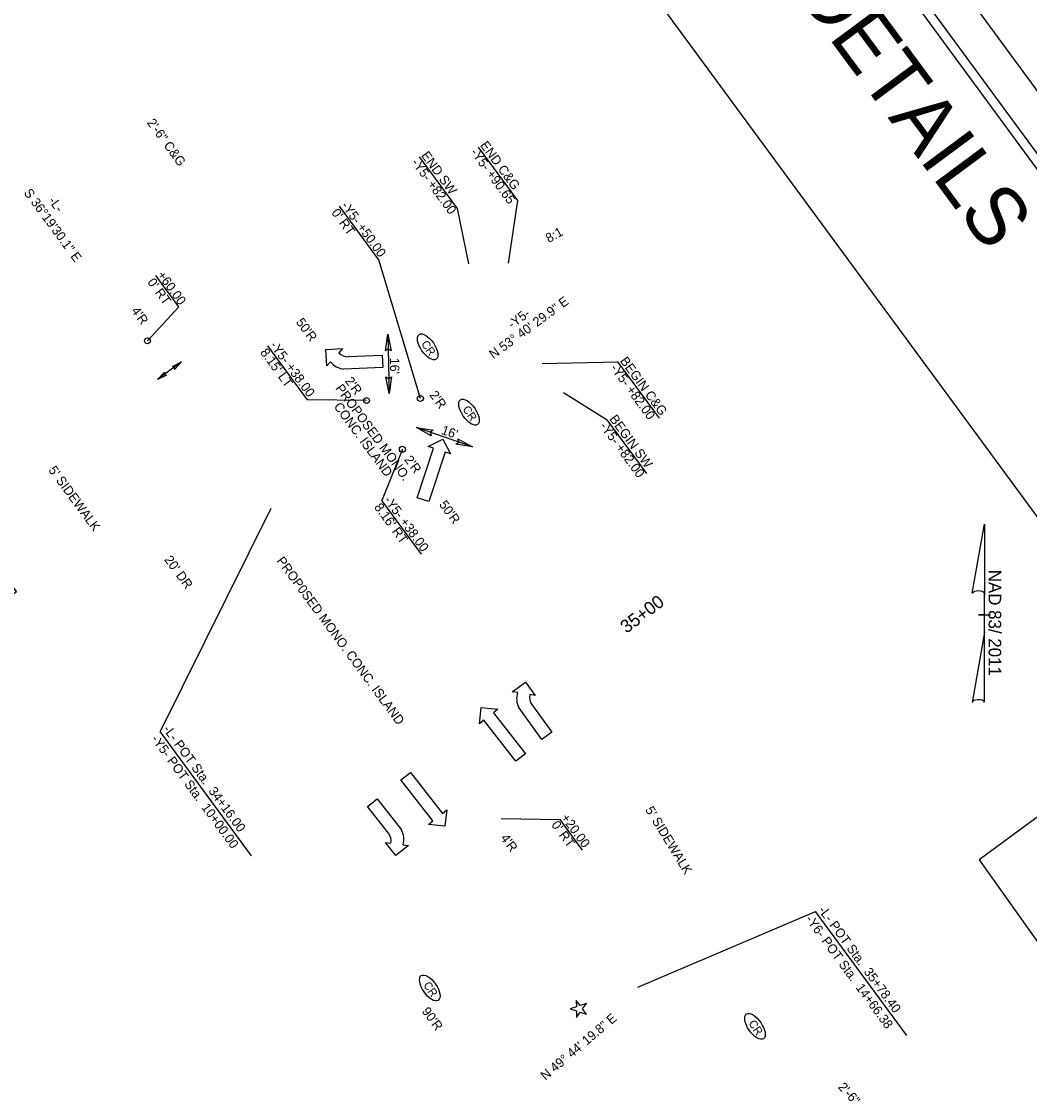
# Model space of a CAD drawing. Extents: x 1763480 to 1764420, y 711010 to 712012.
# Drawn here: x 1763983.9 to 1764255.2, y 711284 to 711573.4 of the extents above; entities that cross this region are included whole.
import ezdxf

# ---------------------------------------------------------------- set-up
doc = ezdxf.new("R2010")
doc.units = 0
for name, color, linetype in [('Default', 7, 'Continuous'), ('P-WATER', 7, 'Continuous'), ('Prop Conc 4in Sidewalk', 7, 'Continuous'), ('Prop Grid Mask', 7, 'Continuous'), ('Prop Horizontal Alignment Direction Label', 7, 'Continuous'), ('Prop Horizontal Alignment Station Label', 7, 'Continuous'), ('Prop Horizontal Alignment Tick Label', 7, 'Continuous'), ('Prop Lane Arrow CELL', 7, 'Continuous'), ('Prop North Arrow NAD83 for Plan Sheets CELL', 7, 'Continuous'), ('Prop RDY Traffic Signal CELL', 7, 'Continuous'), ('Prop Rem of Exist Asph Pvmt', 7, 'Continuous'), ('Prop Terminator CELL', 7, 'Continuous'), ('Prop WCC CELL', 7, 'Continuous'), ('Sheet Plot Border Inside CELL', 7, 'Continuous'), ('Sheet Plot Border Outside CELL', 7, 'Continuous')]:
    doc.layers.add(name, color=color, linetype=linetype)

msp = doc.modelspace()

# ---------------------------------------------------------------- linework, layer by layer
at = {"layer": 'P-WATER'}
msp.add_lwpolyline([(1764402.04, 711336.79), (1763957.77, 711941.04), (1763535.55, 711630.61), (1763979.82, 711026.35)], close=True, dxfattribs=at)
at = {"layer": 'Prop Conc 4in Sidewalk'}
for p, q in [((1764101.28, 711523.01), (1764091, 711536.96)), ((1764104.31, 711508.19), (1764101.28, 711523.01)), ((1764129.78, 711473.55), (1764141.52, 711466.2)), ((1764152.22, 711451.69), (1764141.52, 711466.2))]:
    msp.add_line(p, q, dxfattribs=at)
at = {"layer": 'Prop Grid Mask'}
for p, q in [((1764117.5, 711525.24), (1764106.92, 711539.59)), ((1764114.96, 711508.32), (1764117.5, 711525.24)), ((1764080.11, 711509.26), (1764069.53, 711523.66)), ((1764091.27, 711471.92), (1764080.11, 711509.26)), ((1764026.23, 711496.57), (1764020.05, 711504.98)), ((1764017.81, 711487.42), (1764026.23, 711496.57)), ((1764082.53, 711489.22), (1764082.85, 711473.23)), ((1764060.88, 711471.54), (1764050.18, 711486.1)), ((1764026.96, 711481.73), (1764020.51, 711476.99)), ((1764124.07, 711481.32), (1764144.43, 711481.77)), ((1764155.59, 711466.63), (1764144.43, 711481.77)), ((1764076.77, 711471.38), (1764060.88, 711471.54)), ((1764105.33, 711458.86), (1764090.21, 711464.09)), ((1764086.43, 711458.24), (1764080.93, 711444.46)), ((1764091.56, 711430.01), (1764080.93, 711444.46)), ((1764113.05, 711358.86), (1764128.88, 711358.63)), ((1764134.94, 711350.38), (1764128.88, 711358.63))]:
    msp.add_line(p, q, dxfattribs=at)
for centre in [(1764017.81, 711487.42), (1764076.77, 711471.38), (1764091.27, 711471.92), (1764086.43, 711458.24)]:
    msp.add_circle(centre, 0.802, dxfattribs=at)
at = {"layer": 'Prop Horizontal Alignment Station Label'}
msp.add_lwpolyline([(1763957.77, 711941.04), (1764052.94, 711811.6), (1764008.24, 711778.74), (1764295.85, 711387.56), (1764241.65, 711347.71), (1764301.88, 711263.14), (1763979.82, 711026.35), (1763792.92, 711280.55), (1763982.56, 711419.98), (1763871.46, 711571.1), (1763681.82, 711431.66), (1763535.55, 711630.61)], close=True, dxfattribs=at)
at = {"layer": 'Prop Lane Arrow CELL'}
for p, q in [((1764065.85, 711485.09), (1764070.34, 711485.32)), ((1764066.07, 711480.7), (1764065.85, 711485.09)), ((1764070.34, 711485.32), (1764069.34, 711484.23)), ((1764067.08, 711481.79), (1764066.07, 711480.7)), ((1764071.88, 711483.18), (1764081.02, 711483.54)), ((1764081.02, 711483.54), (1764081.15, 711480.24)), ((1764081.15, 711480.24), (1764070.61, 711479.83)), ((1764093.4, 711458.97), (1764097.33, 711460.99)), ((1764097.33, 711460.99), (1764099.38, 711457)), ((1764090.44, 711445.2), (1764094.82, 711458.5)), ((1764094.82, 711458.5), (1764093.4, 711458.97)), ((1764097.96, 711457.46), (1764093.58, 711444.17)), ((1764099.38, 711457), (1764097.96, 711457.46)), ((1764093.58, 711444.17), (1764090.44, 711445.2)), ((1764115.99, 711392.98), (1764119.54, 711395.59)), ((1764119.54, 711395.59), (1764122.21, 711391.97)), ((1764117.46, 711392.74), (1764115.99, 711392.98)), ((1764122.21, 711391.97), (1764120.74, 711392.21)), ((1764107.15, 711384.38), (1764107.65, 711388.77)), ((1764107.65, 711388.77), (1764112.11, 711388.26)), ((1764112.11, 711388.26), (1764110.93, 711387.34)), ((1764123.94, 711380.16), (1764117.77, 711388.72)), ((1764121.27, 711389.51), (1764126.61, 711382.08)), ((1764108.33, 711385.31), (1764107.15, 711384.38)), ((1764116.96, 711374.28), (1764108.33, 711385.31)), ((1764110.93, 711387.34), (1764119.56, 711376.31)), ((1764126.61, 711382.08), (1764123.94, 711380.16)), ((1764119.56, 711376.31), (1764116.96, 711374.28)), ((1764086.01, 711369.26), (1764088.61, 711371.29)), ((1764088.61, 711371.29), (1764097.21, 711360.24)), ((1764094.61, 711358.21), (1764086.01, 711369.26)), ((1764077.07, 711362.11), (1764079.67, 711364.14)), ((1764082.69, 711354.89), (1764077.07, 711362.11)), ((1764079.67, 711364.14), (1764086.15, 711355.81)), ((1764097.21, 711360.24), (1764098.4, 711361.16)), ((1764098.4, 711361.16), (1764097.88, 711356.77)), ((1764093.42, 711357.29), (1764094.61, 711358.21)), ((1764097.88, 711356.77), (1764093.42, 711357.29)), ((1764084.65, 711348.88), (1764081.84, 711352.4)), ((1764081.84, 711352.4), (1764083.32, 711352.21)), ((1764088.09, 711351.62), (1764084.65, 711348.88)), ((1764086.61, 711351.8), (1764088.09, 711351.62))]:
    msp.add_line(p, q, dxfattribs=at)
for centre, radius, start, end in [((1764071.74, 711486.44), 3.28, 222.6011, 272.2592), ((1764071.2, 711485.03), 5.25, 218.2715, 263.5832), ((1764122.43, 711391.1), 5.25, 161.7658, 207.0775), ((1764123.91, 711391.42), 3.27, 166.0954, 215.7536), ((1764080.12, 711352.88), 3.27, 348.2443, 37.9025), ((1764081.58, 711353.26), 5.25, 343.9147, 29.2264)]:
    msp.add_arc(centre, radius, start, end, dxfattribs=at)
at = {"layer": 'Prop North Arrow NAD83 for Plan Sheets CELL'}
for p, q in [((1764239.82, 711419.53), (1764243.1, 711438.07)), ((1764243.12, 711438.07), (1764243.12, 711418.95)), ((1764243.12, 711409.03), (1764243.12, 711419.51)), ((1764243.12, 711418.95), (1764243.12, 711419.49)), ((1764241.52, 711413.67), (1764241.5, 711413.67)), ((1764242.94, 711413.67), (1764241.52, 711413.67)), ((1764241.54, 711413.67), (1764244.74, 711413.67)), ((1764243.12, 711409.03), (1764239.78, 711390.13)), ((1764243.14, 711390.21), (1764243.12, 711409.03))]:
    msp.add_line(p, q, dxfattribs=at)
for centre, start_param, end_param in [((1764241.48, 711419.33), 0.216388, 2.908219), ((1764241.48, 711390.06), 0.201328, 3.141593)]:
    msp.add_ellipse(centre, major_axis=(1.69, -0.01), ratio=0.461098, start_param=start_param, end_param=end_param, dxfattribs=at)
at = {"layer": 'Prop RDY Traffic Signal CELL'}
msp.add_lwpolyline([(1764134.29, 711308.5), (1764133.24, 711309.92), (1764133.25, 711308.16), (1764131.57, 711307.6), (1764133.25, 711307.06), (1764133.26, 711305.29), (1764134.3, 711306.73), (1764135.98, 711306.19), (1764134.93, 711307.61), (1764135.97, 711309.05), (1764134.29, 711308.5)], dxfattribs=at)
at = {"layer": 'Prop Rem of Exist Asph Pvmt'}
for p, q in [((1764050.98, 711442.3), (1764021.22, 711382.27)), ((1764045.84, 711348.78), (1764021.22, 711382.27)), ((1764149.82, 711313.49), (1764197.6, 711333.85)), ((1764222.17, 711300.43), (1764197.58, 711333.87))]:
    msp.add_line(p, q, dxfattribs=at)
at = {"layer": 'Prop Terminator CELL'}
for points in [[(1764081.84, 711484.71), (1764082.53, 711489.22), (1764083.42, 711484.72), (1764082.61, 711485.28)], [(1764024.51, 711480.51), (1764026.96, 711481.73), (1764025.05, 711479.74), (1764025.05, 711480.33)], [(1764022.96, 711478.22), (1764020.51, 711476.99), (1764022.41, 711478.99), (1764022.42, 711478.4)], [(1764083.54, 711477.74), (1764082.85, 711473.23), (1764081.96, 711477.74), (1764082.77, 711477.18)], [(1764094.21, 711461.89), (1764090.21, 711464.09), (1764094.75, 711463.37), (1764093.94, 711462.8)], [(1764101.33, 711461.07), (1764105.33, 711458.86), (1764100.79, 711459.59), (1764101.6, 711460.15)]]:
    msp.add_lwpolyline(points, close=True, dxfattribs=at)
at = {"layer": 'Prop WCC CELL'}
for centre in [(1764093.23, 711485.8), (1764104.36, 711468.23), (1764093.8, 711313.25), (1764181.33, 711302.92)]:
    msp.add_ellipse(centre, major_axis=(2.29, -3.33), ratio=0.462467, dxfattribs=at)
at = {"layer": 'Sheet Plot Border Inside CELL'}
msp.add_lwpolyline([(1763491.78, 711688.55), (1763985.22, 711017.43), (1764410.21, 711329.9), (1763916.77, 712001.02)], close=True, dxfattribs=at)
at = {"layer": 'Sheet Plot Border Outside CELL'}
msp.add_lwpolyline([(1763479.87, 711687.86), (1763978.5, 711009.69), (1764419.6, 711334.01), (1763920.98, 712012.18)], close=True, dxfattribs=at)

# ---------------------------------------------------------------- texts
at = {"layer": 'Default'}
msp.add_text('INTERSECTION / ISLAND DETAILS', height=15.75, rotation=306.5634, dxfattribs=at).set_placement((1764039.21, 711787.22))
at = {"layer": 'Prop Conc 4in Sidewalk'}
for s, rotation, p in [('END SW', 306.3875, (1764091.36, 711537.29)), ('-Y5- +82.00', 306.3875, (1764088.74, 711535.36)), ('BEGIN SW', 306.3875, (1764142.03, 711466.39)), ('-Y5- +82.00', 306.3875, (1764139.41, 711464.46)), ("5' SIDEWALK", 306.3161, (1763991.04, 711452.62)), ("5' SIDEWALK", 301.453, (1764151.69, 711361.21))]:
    msp.add_text(s, height=2.5, rotation=rotation, dxfattribs=at).set_placement(p)
at = {"layer": 'Prop Grid Mask'}
for s, rotation, p in [('2\'-6" C&G', 306.2561, (1764017.55, 711546.12)), ('-Y5- +90.65', 306.3875, (1764104.61, 711538.12)), ('END C&G', 306.3875, (1764107.23, 711540.05)), ('-Y5- +50.00', 306.325, (1764069.82, 711523.82)), ("0' RT", 306.325, (1764067.2, 711521.89)), ('8:1', 29.1443, (1764125.85, 711513.74)), ("0' RT", 306.325, (1764017.67, 711503.17)), ('+60.00', 306.325, (1764020.29, 711505.1)), ("4'R", 306.325, (1764013.33, 711495.48)), ("50'R", 306.325, (1764057.65, 711492.43)), ('-Y5- +38.00', 306.325, (1764050.65, 711486.2)), ("8.15' LT", 306.325, (1764048.03, 711484.28)), ("16'", 271.1708, (1764083.06, 711482.84)), ('BEGIN C&G', 306.3875, (1764144.87, 711482.01)), ('-Y5- +82.00', 306.3875, (1764142.25, 711480.08)), ('PROPOSED MONO.', 306.4003, (1764068.27, 711474.61)), ("2'R", 306.325, (1764070.87, 711476.61)), ("2'R", 306.325, (1764093.58, 711472.84)), ('CONC. ISLAND', 306.4003, (1764067.84, 711469.72)), ("16'", 340.938, (1764096.71, 711462.41)), ("2'R", 306.325, (1764086.83, 711455.44)), ("8.16' RT", 306.325, (1764078.71, 711442.62)), ('-Y5- +38.00', 306.325, (1764081.33, 711444.54)), ("50'R", 306.325, (1764096.18, 711443.33)), ("20' DR", 306.325, (1764022.21, 711428.53)), ('PROP0SED MONO. CONC. ISLAND', 306.4003, (1764052.43, 711428.2)), ('+20.00', 306.325, (1764129.01, 711359.05)), ("0' RT", 306.325, (1764126.39, 711357.13)), ("4'R", 306.325, (1764112.71, 711353.59)), ("90'R", 306.325, (1764091.51, 711306.97)), ('2\'-6" C&G', 312.4962, (1764203.54, 711286.45))]:
    msp.add_text(s, height=2.5, rotation=rotation, dxfattribs=at).set_placement(p)
at = {"layer": 'Prop Horizontal Alignment Direction Label'}
for s, rotation, p in [('S 36%%d19\'30.1" E', 306.325, (1763984.41, 711527.26)), ('-L-', 306.325, (1763991.05, 711525.09)), ('N 53%%d 40\' 29.9" E', 36.325, (1764110.91, 711482.45)), ('-Y5-', 36.325, (1764115.94, 711490.57)), ('N 49%%d 44\' 19.8" E', 40.2612, (1764124.92, 711288.27))]:
    msp.add_text(s, height=2.5, rotation=rotation, dxfattribs=at).set_placement(p)
at = {"layer": 'Prop Horizontal Alignment Tick Label'}
msp.add_text('35+00', height=3.5, rotation=37.1493, dxfattribs=at).set_placement((1764146.76, 711408.55))
at = {"layer": 'Prop North Arrow NAD83 for Plan Sheets CELL'}
msp.add_text('NAD 83/ 2011', height=3.4, rotation=270, dxfattribs=at).set_placement((1764244.21, 711425.81))
at = {"layer": 'Prop Rem of Exist Asph Pvmt'}
for s, p in [('-L- POT Sta.  34+16.00', (1764021.89, 711382.86)), ('-Y5- POT Sta.  10+00.00', (1764018.69, 711380.23)), ('-L- POT Sta.  35+78.40', (1764198.26, 711334.2)), ('-Y6- POT Sta.  14+66.38', (1764194.81, 711331.73))]:
    msp.add_text(s, height=2.5, rotation=306.325, dxfattribs=at).set_placement(p)
at = {"layer": 'Prop WCC CELL'}
for p in [(1764091.39, 711486.6), (1764102.52, 711469.03), (1764091.96, 711314.04), (1764179.49, 711303.71)]:
    msp.add_text('CR', height=2.16, rotation=304.4873, dxfattribs=at).set_placement(p)

doc.saveas('drawing.dxf')
